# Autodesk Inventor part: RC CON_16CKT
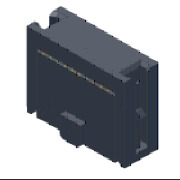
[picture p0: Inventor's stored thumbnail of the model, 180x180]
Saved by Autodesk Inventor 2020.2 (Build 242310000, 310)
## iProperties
Manager: www.cadconsulting.pl
Company: Fabian Stasiak CAD Consulting
Created: 2014-02
Part Number: RC CON_16CKT
Material: Ogólny
Description: Podziałka 2.54mm (0.10cala), gniazdo, pionowe, dwurzędowe
Document SubType Name: Modeling
Designer: F.Stasiak
Language: pl-PL
Size Designation: Ribbon Cable Connector-04
Categories: <MemberInstance><Categories><Category DisplayName="Kable i wiązki przewodów" InternalName="e4a7e005-5e42-4d16-b293-125e7f0d0512" Mnemonic="CABLEANDHARNESS"><Cat
Density: 1 g/cm^3
Appearance: Dark Gray
Catalog Web Link: www.expertbooks.pl
IsCustomPart: 0
Author: F.Stasiak
Subject: Zbiór ćwiczeń. Autodesk Inventor 2020. Kurs Professional
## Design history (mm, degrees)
sketch "Sketch1"
  geometry: L1 (10.79, -3)-(-10.79, -3); L2 (-10.04, -1.5)-(-10.04, -2.1); L3 (-10.79, -3)-(-10.79, -2.1); L4 (-10.04, -2.1)-(-10.79, -2.1); L5 (-10.79, -1.5)-(-10.04, -1.5); L6 (-10.79, -1.5)-(-10.79, 3); L7 (10.04, 1.5)-(10.04, 2.1); L8 (10.79, 1.5)-(10.79, -3); L9 (10.79, 1.5)-(10.04, 1.5); L10 (10.04, 2.1)-(10.79, 2.1); L11 (10.79, 3)-(10.79, 2.1); L12 (0, 3)-(0, -3); L13 (-10.79, 3)-(10.79, 3); 2 further points
  constraints: 26 end point, 8 parallel, 3 midpoint, 3 perpendicular, 2 horizontal, 1 coincident
  dimensions: "d0" = 21.58 distance of L1.start L1.end (derived); "d1" = 6 distance of L1.end L6.end; "d4" = 0.9 distance between parallel lines of L1 L4; "d5" = 0.75 distance of L2.end L3.end; "d6" = 0.6 distance of L2.start L2.end; "d8" = 0.75 distance of L7.end L10.end; "d9" = 0.6 distance of L7.start L7.end; "d10" = 6 distance of L1.start L11.start; "d12" = 0.9 distance of L11.start L10.end
extrude "Wyciągnięcie1" new body sketch "Sketch1" distance "d13" = 10.2; taper "d14" = 0 deg
sketch "Sketch2"
  geometry: L1 (0, 0)-(21.58, 0) reference; L2 (8.99, 3.6)-(12.59, 3.6); L3 (12.59, 3.6)-(12.59, 0.5); L4 (12.09, 0)-(9.49, 0); L5 (8.99, 0.5)-(8.99, 3.6); L6 (8.99, 0.5)-(9.49, 0); L7 (12.59, 0.5)-(12.09, 0); 1 further point
  constraints: 12 end point, 2 midpoint, 2 parallel, 1 horizontal, 1 perpendicular
  dimensions: "d15" = 3.6 distance of L2.start L2.end; "d17" = 0.5 horizontal distance of L4.end L5.start; "d19" = 135 deg angle of L6 L5; "d20" = 135 deg angle of L7 L3; "d21" = 0.5 horizontal distance of L4.start L3.end; "d22" = 3.6 distance between parallel lines of L1 L2
extrude "Wyciągnięcie2" join sketch "Sketch2" distance "d23" = 1; taper "d24" = 0 deg
sketch "Sketch3"
  geometry: L1 (-10.79, 3.6)-(-11.04, 3.6); L2 (-11.79, 2.1)-(-11.79, 1.22); L3 (-11.79, 1.22)-(-10.79, 1.22); L4 (-10.79, 1.22)-(-10.79, 3.6); L5 (10.79, 10.2)-(-10.79, 10.2) reference; L6 (0, 10.2)-(0, 0); L7 (-10.79, 0)-(10.79, 0) reference; L8 (-11.04, 3.6)-(-11.79, 2.1); L9 (10.79, 3.6)-(11.04, 3.6); L10 (11.79, 2.1)-(11.79, 1.22); L11 (11.79, 1.22)-(10.79, 1.22); L12 (10.79, 1.22)-(10.79, 3.6); L13 (11.04, 3.6)-(11.79, 2.1)
  constraints: 22 end point, 5 symmetric about line, 2 midpoint, 2 parallel, 2 perpendicular, 1 horizontal
  dimensions: "d25" = 21.58 diameter of L4 L6 (derived); "d26" = 1.22 distance between parallel lines of L3 L7; "d28" = 1 distance of L2.end L3.end; "d29" = 1.5 vertical distance of L1.end L2.start; "d30" = 0.88 distance of L2.start L2.end; "d31" = 0.25 distance of L1.start L1.end
extrude "Wyciągnięcie3" join sketch "Sketch3" stored distance "d32" = 1; taper "d33" = 0 deg
sketch "Sketch4"
  geometry: L1 (10.79, 3.6)-(11.04, 3.6) reference; L2 (10.79, 6.263)-(11.04, 6.263); L3 (11.79, 5.513)-(11.79, 5.263); L4 (11.79, 5.263)-(10.79, 5.263); L5 (10.79, 5.263)-(10.79, 6.263); L6 (-10.79, 10.2)-(10.79, 10.2) reference; L7 (10.79, 0)-(-10.79, 0) reference; L8 (0, 10.2)-(0, 0); L9 (11.04, 6.263)-(11.79, 5.513); L10 (-10.79, 5.263)-(-10.79, 6.263); L11 (-10.79, 6.263)-(-11.04, 6.263); L12 (-11.04, 6.263)-(-11.79, 5.513); L13 (-11.79, 5.513)-(-11.79, 5.263); L14 (-11.79, 5.263)-(-10.79, 5.263)
  constraints: 22 end point, 5 symmetric about line, 2 midpoint, 2 parallel, 1 horizontal, 1 perpendicular
  dimensions: "d34" = 1.663 distance between parallel lines of L4 L1; "d35" = 21.58 diameter of L5 L8 (derived); "d36" = 1 distance of L3.end L4.end; "d38" = 0.25 distance of L2.start L2.end; "d39" = 1 distance of L4.end L2.start; "d40" = 0.25 distance of L3.start L3.end
extrude "Wyciągnięcie4" join sketch "Sketch4" distance "d41" = 1; taper "d42" = 0 deg
sketch "Sketch5"
  geometry: L1 (11.04, -3.6)-(10.79, -3.6) reference; L2 (11.04, -6.263)-(10.79, -6.263); L3 (10.79, -6.263)-(10.79, -5.263); L4 (10.79, -5.263)-(11.79, -5.263); L5 (11.79, -5.263)-(11.79, -5.513); L6 (10.79, -10.2)-(-10.79, -10.2) reference; L7 (1.3, 0)-(-1.3, 0) reference; L8 (0, 0)-(0, -10.2); L9 (11.04, -6.263)-(11.79, -5.513); L10 (-10.79, -6.263)-(-10.79, -5.263); L11 (-11.04, -6.263)-(-10.79, -6.263); L12 (-11.04, -6.263)-(-11.79, -5.513); L13 (-11.79, -5.263)-(-11.79, -5.513); L14 (-10.79, -5.263)-(-11.79, -5.263)
  constraints: 22 end point, 5 symmetric about line, 2 midpoint, 2 parallel, 1 horizontal, 1 perpendicular
  dimensions: "d43" = 1.663 distance between parallel lines of L1 L4; "d44" = 21.58 diameter of L3 L8 (derived); "d45" = 1 distance of L2.end L3.end; "d46" = 1 distance of L3.end L4.end; "d47" = 0.25 distance of L2.start L2.end; "d48" = 0.25 distance of L4.end L5.end
extrude "Wyciągnięcie5" join sketch "Sketch5" distance "d49" = 1; taper "d50" = 0 deg
sketch "Sketch6"
  geometry: L1 (0, -10.2)-(9.49, -10.2) reference; L2 (-36.97, -6.736)-(-34.97, -10.2); L3 (-38.97, -10.2)-(-36.97, -6.736); L4 (-38.97, -10.2)-(-34.97, -10.2); L5 (0.5, -10.2)-(2.5, -6.736); L6 (2.5, -6.736)-(4.5, -10.2); L7 (0.5, -10.2)-(4.5, -10.2)
  constraints: 12 end point, 4 equal length, 2 point on line, 1 collinear
  dimensions: "d61" = 0.5 distance of L5.start L1.start; "d62" = 4 distance of L5.start L6.end
extrude "Wyciągnięcie6" cut sketch "Sketch6" distance "d63" = 0.1; taper "d64" = 0 deg
sketch "Sketch7"
  geometry: L1 (10.79, 3)-(10.79, -1.5) reference; L2 (8.515, 1.645)-(9.265, 1.645); L3 (9.265, 1.645)-(9.265, 0.895); L4 (9.265, 0.895)-(8.515, 0.895); L5 (8.515, 0.895)-(8.515, 1.645); L6 (8.515, -0.895)-(9.265, -0.895); L7 (9.265, -0.895)-(9.265, -1.645); L8 (9.265, -1.645)-(8.515, -1.645); L9 (8.515, -1.645)-(8.515, -0.895); L10 (8.89, 0.895)-(8.89, -0.895); 2 further points
  constraints: 18 end point, 7 equal length, 4 parallel, 3 midpoint, 3 perpendicular, 2 horizontal, 1 horizontal alignment
  dimensions: "d65" = 0.75 distance of L2.start L2.end; "d66" = 2.54 distance between parallel lines of L6 L2; "d67" = 1.525 distance between parallel lines of L1 L7
extrude "Wyciągnięcie7" cut sketch "Sketch7" distance "d68" = 3; taper "d69" = 0 deg
pattern_linear "Wzór prostokątny1" dims "d75" = 2.54
workplane "Work Plane1"
sketch "Sketch8"
  geometry: L1 (-11.771, -1.499)-(-10.92, -1.499); L2 (-12.475, -1.03)-(-11.771, -1.499); L3 (-12.475, -3.03)-(-12.475, -1.03); L4 (12.475, -3.03)-(-12.475, -3.03); L5 (-12.475, 3.03)-(12.475, 3.03); L6 (-10.92, -1.499)-(-10.92, 1.499); L7 (-10.79, 3)-(10.79, 3) reference; L8 (-10.79, -1.5)-(-10.79, 3) reference; L9 (-10.04, -1.5)-(-10.79, -1.5) reference; L10 (-10.04, -2.1)-(-10.04, -1.5) reference; L11 (-10.79, -2.1)-(-10.04, -2.1) reference; L12 (-10.79, -3)-(-10.79, -2.1) reference; L13 (10.79, -3)-(-10.79, -3) reference; L14 (10.79, 1.5)-(10.79, -3) reference; L15 (10.04, 1.5)-(10.79, 1.5) reference; L16 (10.04, 2.1)-(10.04, 1.5) reference; L17 (10.79, 2.1)-(10.04, 2.1) reference; L18 (10.79, 3)-(10.79, 2.1) reference; L19 (0, 3)-(0, -3); L20 (-10.92, 0)-(-42.954, 0); L21 (-12.475, 1.03)-(-11.771, 1.499); L22 (-12.475, 3.03)-(-12.475, 1.03); L23 (-11.771, 1.499)-(-10.92, 1.499); L24 (12.475, 3.03)-(12.475, 1.03); L25 (12.475, 1.03)-(11.771, 1.499); L26 (11.771, 1.499)-(10.92, 1.499); L27 (10.92, -1.499)-(10.92, 1.499); L28 (11.771, -1.499)-(10.92, -1.499); L29 (12.475, -1.03)-(11.771, -1.499); L30 (12.475, -3.03)-(12.475, -1.03); 4 further points
  constraints: 36 end point, 8 symmetric about line, 5 midpoint, 4 perpendicular, 3 parallel, 1 coincident, 1 horizontal, 1 horizontal alignment
  dimensions: "d160" = 2 distance of L3.start L2.start; "d161" = 0.85079 distance of L1.start L1.end; "d162" = 2.99894 distance of L1.end L6.end; "d163" = 56.3099 deg angle of L3 L2; "d164" = 0.13 distance between parallel lines of L8 L6; "d165" = 24.95 distance of L5.start L5.end (derived)
extrude "Wyciągnięcie8" join sketch "Sketch8" distance "d90" = 2.5; taper "d91" = 0 deg
sketch "Sketch10"
  geometry: L1 (-12.475, 3.03)-(-12.475, 1.03) reference; L2 (12.475, 3.03)-(-12.475, 3.03) reference; L3 (12.475, 1.03)-(12.475, 3.03) reference; L4 (11.771, 1.499)-(12.475, 1.03) reference; L5 (10.92, 1.499)-(11.771, 1.499) reference; L6 (10.92, -1.499)-(10.92, 1.499) reference; L7 (11.771, -1.499)-(10.92, -1.499) reference; L8 (12.475, -1.03)-(11.771, -1.499) reference; L9 (12.475, -3.03)-(12.475, -1.03) reference; L10 (-12.475, -3.03)-(12.475, -3.03) reference; L11 (-12.475, -1.03)-(-12.475, -3.03) reference; L12 (-11.771, -1.499)-(-12.475, -1.03) reference; L13 (-10.92, -1.499)-(-11.771, -1.499) reference; L14 (-10.92, 1.499)-(-10.92, -1.499) reference; L15 (-11.771, 1.499)-(-10.92, 1.499) reference; L16 (-12.475, 1.03)-(-11.771, 1.499) reference; L17 (10.79, -1.5)-(10.04, -1.5) reference; L18 (10.04, -1.5)-(10.04, -2.1) reference; L19 (10.04, -2.1)-(10.79, -2.1) reference; L20 (-10.79, 1.5)-(-10.04, 1.5) reference; L21 (-10.04, 1.5)-(-10.04, 2.1) reference; L22 (-10.04, 2.1)-(-10.79, 2.1) reference; L23 (-10.8, 1.51)-(-10.05, 1.51); L24 (-10.05, 1.51)-(-10.05, 2.09); L25 (-10.05, 2.09)-(-10.8, 2.09); L26 (-10.8, 2.09)-(-10.8, 3.03); L27 (10.8, -2.09)-(10.05, -2.09); L28 (10.05, -2.09)-(10.05, -1.51); L29 (10.05, -1.51)-(10.8, -1.51); L30 (10.8, -3.03)-(10.8, -2.09); L31 (-10.92, -1.499)-(-10.8, -1.499); L32 (-10.92, 1.499)-(-10.8, 1.499); L33 (-10.8, -3.03)-(-10.8, -1.499); L34 (-10.8, 1.499)-(-10.8, 1.51); L35 (10.92, 1.499)-(10.8, 1.499); L36 (10.92, -1.499)-(10.8, -1.499); L37 (10.8, -1.51)-(10.8, -1.499); L38 (10.8, 1.499)-(10.8, 3.03); 4 further points
  constraints: 32 end point, 8 perpendicular, 7 parallel, 4 midpoint, 4 point on line, 2 horizontal, 2 horizontal alignment
  dimensions: "d167" = 0.01 distance between parallel lines of L20 L23; "d168" = 0.01 distance between parallel lines of L21 L24; "d170" = 0.01 distance from line of L26 L22.end; "d172" = 0.01 distance between parallel lines of L19 L27; "d173" = 0.01 distance between parallel lines of L18 L28; "d174" = 0.01 distance from line of L30 L19.end; "d180" = 0.01 distance from line of L20.start L34; "d181" = 0.12 distance of L13.start L31.end; "d182" = 0.01 distance of L36.end L17.start; "d183" = 0.12 distance of L5.start L35.end
extrude "Wyciągnięcie9" join sketch "Sketch10" distance "d157" = 10.7; taper "d158" = 0 deg
sketch "Sketch12"
  geometry: L1 (12.475, 13.2)-(-12.475, 13.2) reference; L2 (0, 13.2)-(0, 4.865); L3 (-12.475, 13.2)-(-12.475, 0) reference; L4 (-12.475, 0)-(-10.8, 0); L5 (-10.8, 0)-(-10.8, 1.21); L6 (-10.8, 1.21)-(-12.475, 1.21); L7 (-12.475, 1.21)-(-12.475, 0); L8 (-11.04, 3.6)-(-10.79, 3.6) reference; L9 (-11.79, 2.1)-(-11.04, 3.6) reference; L10 (-11.79, 1.22)-(-11.79, 2.1) reference; L11 (-10.79, 1.22)-(-11.79, 1.22) reference; L12 (10.8, 0)-(10.8, 1.21); L13 (10.8, 1.21)-(12.475, 1.21); L14 (12.475, 1.21)-(12.475, 0); L15 (12.475, 0)-(10.8, 0); L16 (-10.79, 3.6)-(-10.79, 1.22) reference
  constraints: 18 end point, 4 symmetric about line, 2 parallel, 2 perpendicular, 1 horizontal, 1 midpoint
  dimensions: "d177" = 0.01 distance between parallel lines of L11 L6; "d243" = 1.675 distance of L3.end L4.end
extrude "Wyciągnięcie10" join sketch "Sketch12" stored distance "d178" = 6.06; taper "d179" = 0 deg
sketch "Sketch20" dims "d253" = 10
  geometry: L1 (24.95, -2.49)-(0, -2.49) reference; L2 (24.95, 0)-(24.95, -2.49) reference; L3 (24.95, 0)-(0, 0) reference; L4 (0, 0)-(0, -2.49) reference; L5 (23.265, -3)-(1.685, -3) reference; 68 further points
  constraints: 2 midpoint, 2 vertical alignment, 1 horizontal, 63 other
  dimensions: "d240" = 0.25 distance from line of L5 point (2.95, -2.75); "d241" = 0.25 distance from line of L5 point (12.475, -2.75); "d242" = 0.25 distance from line of L3 point (12.475, 0.25); "d247" = 9.525 distance of point (12.475, -2.75) point (2.95, -2.75) (derived); "d250" = 1.27 distance of point (2.95, -2.75) point (4.22, -2.75)
sketch "Sketch21"
  geometry: L1 (0, 2.49)-(24.95, 2.49) reference; L2 (0, 2.49)-(0, 0) reference; L3 (0, 0)-(24.95, 0) reference; L4 (24.95, 0)-(24.95, 2.49) reference; 2 further points
workpoint "Work Point1"
workpoint "Work Point2"
node "1"
node "2"
node "3"
node "4"
node "5"
node "6"
node "7"
node "8"
node "9"
node "10"
node "11"
node "12"
node "13"
node "14"
node "15"
node "16"
body "Solid1"
chamfer "Faza1" distance "d70" = 0.5; stored, may be unused: second distance "d71" = 2, angle "d72" = 45 deg
chamfer "Faza2" distance "d185" = 1; stored, may be unused: second distance "d186" = 2, angle "d187" = 45 deg
chamfer "Faza3" distance "d188" = 1.749; stored, may be unused: second distance "d189" = 2, angle "d190" = 45 deg
chamfer "Faza4" distance "d191" = 10.71; stored, may be unused: second distance "d192" = 0.03, angle "d193" = 45 deg
chamfer "Faza5" distance "d194" = 10.71; stored, may be unused: second distance "d195" = 0.03, angle "d196" = 45 deg
chamfer "Faza8" distance "d203" = 0.5; stored, may be unused: second distance "d204" = 0.03, angle "d205" = 45 deg
node "Projected Loop2"
node "Projected Loop3"
node "Projected Loop4"
other parameters: "DimA" = 21.58 [user parameter], "DimB" = 24.95 [user parameter], "DimC" = 9.525 [user parameter], "d123" = 0.01, "d126" = 0.01, "d148" = 0.01, "d152" = 0.01, "d166" = 0.01, "d169" = 0.01, "d171" = 0.01, "d175" = 0.01, "d234" = 10.7
